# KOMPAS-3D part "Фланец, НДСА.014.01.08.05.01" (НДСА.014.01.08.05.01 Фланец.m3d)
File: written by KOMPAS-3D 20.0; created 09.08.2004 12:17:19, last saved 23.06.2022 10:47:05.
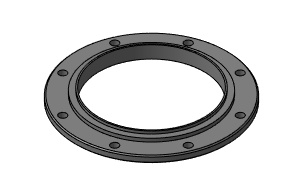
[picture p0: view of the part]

Document properties: Автор: Устинов А.В.; Организация: Эсто-вакуум; Полное имя файла: C:\Users\cherbakova\Desktop\PLM\НДСА.014.01.08.05.01 Фланец.m3d

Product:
- Part/product: Фланец  | designation НДСА.014.01.08.05.01
    Материал: Сталь 20 ГОСТ 1050-88 (density 7859 kg/m3)
    Масса: 1.90963
    additional columns: <item xmlns="http://appius.ru/pdm" xmlns:xs="http://www.w3.org/2001/XMLSchema" x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; <item xmlns="http://appius.ru/pdm" xmlns:xs="http://www.w3.org/2001/XMLSchema" x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; <item xmlns="http://appius.ru/pdm" xmlns:xs="http://www.w3.org/2001/XMLSchema" x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; <item xmlns="http://appius.ru/pdm" xmlns:xs="http://www.w3.org/2001/XMLSchema" x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; <item xmlns="http://appius.ru/pdm" xmlns:xs="http://www.w3.org/2001/XMLSchema" x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; <item xmlns="http://appius.ru/pdm" xmlns:xs="http://www.w3.org/2001/XMLSchema" x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
    source file: НДСА.014.01.08.05.01 Фланец.CDW

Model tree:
1. Плоскость XY
2. Плоскость ZX
3. Плоскость ZY
4. Начало координат
5. Эскиз:1
6. Операция выдавливания:1
     Расстояние 1 = 10
7. Эскиз:2  (labels: Операция выдавливания:1; Операция выдавливания:1)
8. Приклеить элемент выдавливания:1
     Расстояние 1 = 5
9. Эскиз:3  (labels: Приклеить элемент выдавливания:1; Приклеить элемент выдавливания:1)
10. Приклеить элемент выдавливания:2
     Расстояние 1 = 4
11. Эскиз:4  (labels: Приклеить элемент выдавливания:2; Приклеить элемент выдавливания:2)
12. Вырезать элемент выдавливания:1
     Расстояние 2 = 19
13. Эскиз:5  (labels: Операция выдавливания:1)
14. Вырезать элемент выдавливания:2
     Расстояние 2 = 10
15. Фаска:1  (labels: Операция выдавливания:1; Операция выдавливания:1; Сталь 20 ГОСТ 1050-88)
     Угол = 45; Длина 1 = 1.6; Длина 2 = 1.6

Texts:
  НДСА.014.01.08.05.01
